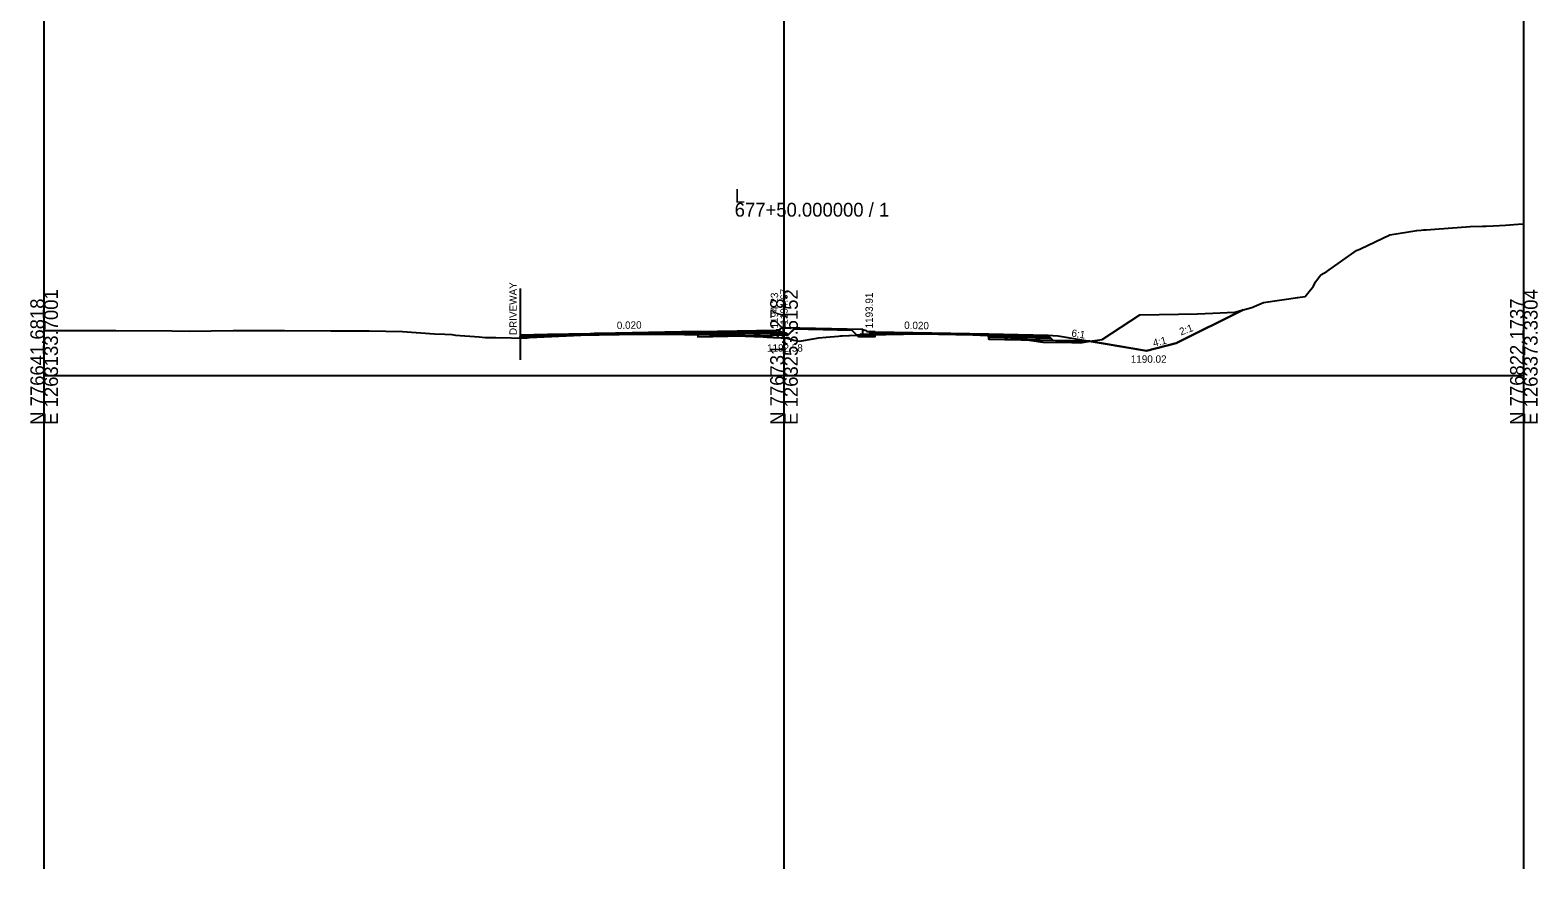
# Model space of a CAD drawing. Extents: x -41 to 1262860, y -100 to 777489.
# Drawn here: x 497.2 to 802.8, y 2050 to 2220 of the extents above; entities that cross this region are included whole.
import ezdxf

# ---------------------------------------------------------------- set-up
doc = ezdxf.new("R2010")
doc.units = 0
for name, color, linetype in [('Exist Cross Section Cell', 7, 'Continuous'), ('Exist XS Center Line Elevation Label', 7, 'Continuous'), ('Exist XS Ground Line', 7, 'Continuous'), ('Prop CMT Pvmt Course 1', 7, 'Continuous'), ('Prop CMT Pvmt Surface', 7, 'Continuous'), ('Prop CMT Shear Line', 7, 'Continuous'), ('Prop CMT Shld Paved Course 1', 7, 'Continuous'), ('Prop CMT Shld Paved Course 2', 7, 'Continuous'), ('Prop CMT Shld Paved Course 4', 7, 'Continuous'), ('Prop CMT Subgrade Earthwork', 7, 'Continuous'), ('Prop Conc Curb and Gutter', 7, 'Continuous'), ('Prop Conc Island Cover', 7, 'Continuous'), ('Prop XS Ditch Standard Text', 7, 'Continuous'), ('Prop XS Earthwork Shape', 7, 'Continuous'), ('Prop XS Elevation Labels', 7, 'Continuous'), ('Prop XS Exc Vertical Line 1', 7, 'Continuous'), ('Prop XS Exc Vertical Line 2', 7, 'Continuous'), ('Prop XS Exc Vertical Line 3', 7, 'Continuous'), ('Prop XS Finish Grade', 7, 'Continuous'), ('Prop XS Hydro Elevations', 7, 'Continuous'), ('Prop XS SE Text', 7, 'Continuous'), ('Prop XS Side Slope Text', 7, 'Continuous'), ('Scratch_Level_4', 7, 'Continuous'), ('Scratch_Level_6', 7, 'Continuous')]:
    doc.layers.add(name, color=color, linetype=linetype)

msp = doc.modelspace()

# ---------------------------------------------------------------- linework, layer by layer
at = {"layer": 'Exist Cross Section Cell'}
for p, q in [((650, 2150), (650, 2185)), ((500, 2150), (650, 2150)), ((650, 2150), (800, 2150))]:
    msp.add_line(p, q, dxfattribs=at)
at = {"layer": 'Exist XS Ground Line'}
msp.add_lwpolyline([(500, 2159.12), (503.29, 2159.11), (507.58, 2159.1), (514.52, 2159.1), (525.89, 2159.03), (529.43, 2158.99), (538.31, 2159.11), (543.77, 2159.09), (545.28, 2159.11), (546.19, 2159.11), (548.74, 2159.09), (558.13, 2159.05), (559.47, 2159.04), (562.85, 2159.03), (565.88, 2159.02), (572.63, 2158.89), (579.14, 2158.45), (581.2, 2158.39), (582.67, 2158.3), (583.4, 2158.2), (588.19, 2157.86), (589.38, 2157.71), (591.6, 2157.69), (597.83, 2157.56), (597.96, 2157.61), (598.4, 2157.7), (608.81, 2158.17), (611.05, 2158.27), (622.1, 2158.4), (623.45, 2158.41), (624.74, 2158.39), (634.91, 2158.23), (645.76, 2157.81), (646.61, 2157.78), (647.5, 2157.74), (647.56, 2157.74), (648.19, 2157.7), (650.62, 2157.54), (652.02, 2157.16), (653.11, 2156.95), (656.33, 2157.48), (657.02, 2157.61), (658.52, 2157.74), (661.02, 2157.97), (661.46, 2158.02), (661.8, 2158.03), (665.75, 2158.23), (667, 2158.25), (677.89, 2158.42), (688.3, 2158.26), (689.75, 2158.24), (690.25, 2158.2), (695, 2157.82), (697.85, 2157.43), (702.5, 2156.79), (708.34, 2156.68), (710.1, 2156.64), (711.22, 2156.83), (714.5, 2157.27), (722.14, 2162.31), (722.16, 2162.32), (722.18, 2162.32), (733.84, 2162.51), (736.95, 2162.61), (739.88, 2162.79), (741.4, 2162.84), (744.87, 2163.81), (747.25, 2164.82), (754.18, 2165.83), (755.64, 2165.99), (756.21, 2166.67), (757.37, 2168.13), (757.75, 2168.97), (758.86, 2170.4), (760.03, 2171.07), (765.6, 2175.03), (766.05, 2175.33), (766.88, 2175.7), (772.83, 2178.52), (778.29, 2179.4), (779.17, 2179.47), (779.66, 2179.51), (780.17, 2179.54), (781.96, 2179.68), (787.36, 2180.07), (788.28, 2180.13), (789.15, 2180.18), (791.65, 2180.24), (792.38, 2180.28), (793.77, 2180.33), (796.26, 2180.49), (798.83, 2180.65), (800, 2180.72)], dxfattribs=at)
at = {"layer": 'Prop CMT Pvmt Course 1'}
for p, q in [((632.5, 2158.65), (648.39, 2158.97)), ((648.39, 2158.97), (648.39, 2159.22)), ((667.5, 2158.9), (667.5, 2158.65)), ((668.5, 2158.63), (667.5, 2158.65))]:
    msp.add_line(p, q, dxfattribs=at)
for points in [[(596.5, 2158.18), (596.5, 2157.93), (596.5, 2157.93), (602.04, 2158.04), (602.04, 2158.04), (610.72, 2158.21), (610.72, 2158.21), (611.09, 2158.22), (611.09, 2158.22), (611.51, 2158.23), (611.51, 2158.23), (611.93, 2158.24), (611.93, 2158.24), (612.28, 2158.24), (612.28, 2158.24), (612.53, 2158.25), (612.53, 2158.25), (632.5, 2158.65), (632.5, 2158.9), (632.5, 2158.9), (612.53, 2158.5), (612.53, 2158.5), (612.28, 2158.49), (612.28, 2158.49), (611.93, 2158.49), (611.93, 2158.49), (611.51, 2158.48), (611.51, 2158.48), (611.09, 2158.47), (611.09, 2158.47), (610.72, 2158.46), (610.72, 2158.46), (602.04, 2158.29), (602.04, 2158.29), (596.5, 2158.18), (596.5, 2158.18), (596.5, 2158.18)], [(691.5, 2158.42), (691.5, 2158.17), (691.5, 2158.17), (668.5, 2158.63), (668.5, 2158.63), (668.5, 2158.63), (668.5, 2158.63), (668.5, 2158.88), (668.5, 2158.88), (668.5, 2158.88), (668.5, 2158.88), (668.5, 2158.88), (691.5, 2158.42), (691.5, 2158.42), (691.5, 2158.42)]]:
    msp.add_lwpolyline(points, dxfattribs=at)
at = {"layer": 'Prop CMT Pvmt Surface'}
for p, q in [((632.5, 2158.9), (648.39, 2159.22)), ((668.5, 2158.88), (667.5, 2158.9)), ((668.5, 2158.88), (691.5, 2158.42)), ((691.5, 2158.42), (703.5, 2158.18))]:
    msp.add_line(p, q, dxfattribs=at)
msp.add_lwpolyline([(596.5, 2158.18), (596.5, 2158.18), (596.5, 2158.18), (596.5, 2158.18), (596.5, 2158.18), (596.5, 2158.18), (596.5, 2158.18), (596.5, 2158.18), (632.5, 2158.9), (632.5, 2158.9)], dxfattribs=at)
at = {"layer": 'Prop CMT Shear Line'}
msp.add_line((596.5, 2167.62), (596.5, 2153.18), dxfattribs=at)
at = {"layer": 'Prop CMT Shld Paved Course 1'}
for p, q in [((691.5, 2158.42), (691.5, 2158.42)), ((691.5, 2158.42), (691.5, 2158.42)), ((691.5, 2158.42), (691.5, 2158.17)), ((691.5, 2158.17), (691.5, 2158.17)), ((691.5, 2158.17), (703.76, 2157.92)), ((695.5, 2158.34), (695.5, 2158.34)), ((703.76, 2157.92), (703.5, 2158.18))]:
    msp.add_line(p, q, dxfattribs=at)
at = {"layer": 'Prop CMT Shld Paved Course 2'}
for p, q in [((602.04, 2158.04), (608.81, 2158.18)), ((608.81, 2158.17), (602.04, 2157.86)), ((608.81, 2158.18), (610.72, 2158.21)), ((609.11, 2158.18), (608.81, 2158.17)), ((608.81, 2158.18), (608.81, 2158.18)), ((608.81, 2158.18), (608.81, 2158.18)), ((608.81, 2158.17), (608.81, 2158.17)), ((608.81, 2158.17), (608.81, 2158.17)), ((610.72, 2158.21), (609.11, 2158.18)), ((609.11, 2158.18), (609.11, 2158.18)), ((611.05, 2158.22), (610.72, 2158.21)), ((610.72, 2158.21), (611.05, 2158.22)), ((610.72, 2158.21), (610.72, 2158.21)), ((610.72, 2158.21), (610.72, 2158.21)), ((611.09, 2158.22), (611.05, 2158.22)), ((611.05, 2158.22), (611.05, 2158.22)), ((611.05, 2158.22), (611.09, 2158.22)), ((611.51, 2158.23), (611.09, 2158.22)), ((611.09, 2158.22), (611.51, 2158.23)), ((611.93, 2158.24), (611.51, 2158.23)), ((611.51, 2158.23), (611.93, 2158.24)), ((611.51, 2158.23), (611.51, 2158.23)), ((611.51, 2158.23), (611.51, 2158.23)), ((612.28, 2158.24), (611.93, 2158.24)), ((611.93, 2158.24), (611.93, 2158.24)), ((611.93, 2158.24), (611.93, 2158.24)), ((611.93, 2158.24), (612.28, 2158.24)), ((612.53, 2158.25), (612.28, 2158.24)), ((612.28, 2158.24), (612.53, 2158.25)), ((612.28, 2158.24), (612.28, 2158.24)), ((612.28, 2158.24), (612.28, 2158.24)), ((612.53, 2158.25), (622.1, 2158.44)), ((616.98, 2158.34), (612.53, 2158.25)), ((612.53, 2158.25), (612.53, 2158.25)), ((612.53, 2158.25), (612.53, 2158.25)), ((622.1, 2158.4), (616.98, 2158.34)), ((616.98, 2158.34), (616.98, 2158.34)), ((616.98, 2158.34), (616.98, 2158.34)), ((616.98, 2158.34), (616.98, 2158.34)), ((622.1, 2158.44), (623.45, 2158.47)), ((622.1, 2158.44), (622.1, 2158.44)), ((622.1, 2158.44), (622.1, 2158.44)), ((623.45, 2158.41), (622.1, 2158.4)), ((622.1, 2158.4), (622.1, 2158.4)), ((623.45, 2158.47), (624.74, 2158.49)), ((624.74, 2158.39), (623.45, 2158.41)), ((624.74, 2158.49), (632.5, 2158.65)), ((624.74, 2158.49), (624.74, 2158.49)), ((631.18, 2158.29), (624.74, 2158.39)), ((624.74, 2158.39), (624.74, 2158.39)), ((632.5, 2158.32), (631.18, 2158.29)), ((631.18, 2158.29), (631.18, 2158.29)), ((632.5, 2158.65), (632.5, 2158.65)), ((632.5, 2158.65), (632.5, 2158.65)), ((632.5, 2158.65), (632.5, 2158.32)), ((632.5, 2158.32), (648.39, 2158.63)), ((632.5, 2158.32), (632.5, 2158.32)), ((648.39, 2158.97), (648.39, 2158.63)), ((648.39, 2158.63), (648.39, 2158.63)), ((667.5, 2158.32), (667.5, 2158.65)), ((668.5, 2158.3), (667.5, 2158.32)), ((668.5, 2158.3), (668.5, 2158.63)), ((668.5, 2158.63), (668.5, 2158.63)), ((668.5, 2158.63), (668.5, 2158.63)), ((668.5, 2158.63), (668.5, 2158.63)), ((668.5, 2158.63), (677.89, 2158.44)), ((669.15, 2158.28), (668.5, 2158.3)), ((668.5, 2158.3), (668.5, 2158.3)), ((668.5, 2158.3), (668.5, 2158.3)), ((677.89, 2158.42), (669.15, 2158.28)), ((669.15, 2158.28), (669.15, 2158.28)), ((669.15, 2158.28), (669.15, 2158.28)), ((677.89, 2158.44), (677.89, 2158.44)), ((677.89, 2158.44), (677.89, 2158.44)), ((677.89, 2158.44), (677.89, 2158.44)), ((677.89, 2158.44), (677.89, 2158.44)), ((677.89, 2158.44), (688.3, 2158.23)), ((682.75, 2158.34), (677.89, 2158.42)), ((677.89, 2158.42), (677.89, 2158.42)), ((688.3, 2158.23), (682.75, 2158.34)), ((682.75, 2158.34), (682.75, 2158.34)), ((682.75, 2158.34), (682.75, 2158.34)), ((682.75, 2158.34), (682.75, 2158.34)), ((689.75, 2158.2), (688.3, 2158.23)), ((688.3, 2158.23), (688.3, 2158.23)), ((688.3, 2158.23), (688.3, 2158.23)), ((688.3, 2158.23), (688.3, 2158.23)), ((688.3, 2158.23), (688.3, 2158.23)), ((688.3, 2158.23), (689.75, 2158.2)), ((690.25, 2158.19), (689.75, 2158.2)), ((689.75, 2158.2), (689.75, 2158.2)), ((689.75, 2158.2), (689.75, 2158.2)), ((689.75, 2158.2), (690.25, 2158.19)), ((690.25, 2158.19), (690.25, 2158.19)), ((690.25, 2158.19), (691.5, 2158.17)), ((690.39, 2158.19), (690.25, 2158.19)), ((690.25, 2158.19), (690.25, 2158.19)), ((690.25, 2158.19), (690.25, 2158.19)), ((690.25, 2158.19), (690.25, 2158.19)), ((691.5, 2158.1), (690.39, 2158.19)), ((690.39, 2158.19), (690.39, 2158.19)), ((690.39, 2158.19), (690.39, 2158.19)), ((691.5, 2158.17), (691.5, 2158.17)), ((691.5, 2158.17), (691.5, 2158.17)), ((691.5, 2158.17), (691.5, 2157.84)), ((691.5, 2158.17), (691.5, 2158.17)), ((691.5, 2158.17), (691.5, 2158.1)), ((596.5, 2157.93), (597.83, 2157.96)), ((596.5, 2157.6), (596.5, 2157.93)), ((596.5, 2157.93), (596.5, 2157.93)), ((597.83, 2157.62), (596.5, 2157.6)), ((596.5, 2157.6), (596.5, 2157.6)), ((597.83, 2157.96), (597.83, 2157.96)), ((597.83, 2157.96), (597.96, 2157.96)), ((597.96, 2157.63), (597.83, 2157.62)), ((597.83, 2157.62), (597.83, 2157.62)), ((597.96, 2157.96), (598.4, 2157.97)), ((598.04, 2157.63), (597.96, 2157.63)), ((598.4, 2157.7), (598.04, 2157.63)), ((598.04, 2157.63), (598.04, 2157.63)), ((598.4, 2157.97), (602.04, 2158.04)), ((598.4, 2157.97), (598.4, 2157.97)), ((598.4, 2157.97), (598.4, 2157.97)), ((598.4, 2157.97), (598.4, 2157.97)), ((602.04, 2157.86), (598.4, 2157.7)), ((598.4, 2157.7), (598.4, 2157.7)), ((598.4, 2157.7), (598.4, 2157.7)), ((598.4, 2157.7), (598.4, 2157.7)), ((691.5, 2157.84), (691.5, 2157.84)), ((691.5, 2157.84), (704.1, 2157.58)), ((695.76, 2158.08), (695.76, 2158.08)), ((704.1, 2157.58), (703.76, 2157.92))]:
    msp.add_line(p, q, dxfattribs=at)
at = {"layer": 'Prop CMT Shld Paved Course 4'}
for p, q in [((631.18, 2158.29), (632.5, 2158.27)), ((632.5, 2158.32), (632.5, 2157.86)), ((632.5, 2157.86), (650.84, 2158.22)), ((648.39, 2158.63), (650.39, 2158.67)), ((650.39, 2158.67), (650.84, 2158.22)), ((665.5, 2158.36), (665.05, 2157.91)), ((667.5, 2158.32), (665.5, 2158.36)), ((668.5, 2157.84), (668.5, 2158.3)), ((669.15, 2158.28), (668.5, 2158.27)), ((596.5, 2157.59), (596.5, 2157.6)), ((597.83, 2157.56), (596.5, 2157.59)), ((597.96, 2157.61), (597.83, 2157.56)), ((598.04, 2157.63), (597.96, 2157.61)), ((668.5, 2157.84), (665.05, 2157.91)), ((691.5, 2157.84), (691.5, 2157.84)), ((691.5, 2157.84), (691.5, 2157.84)), ((691.5, 2157.84), (691.5, 2157.38)), ((691.5, 2157.38), (704.56, 2157.12)), ((696.1, 2157.74), (696.1, 2157.74)), ((696.6, 2157.73), (696.6, 2157.73)), ((704.56, 2157.12), (704.1, 2157.58))]:
    msp.add_line(p, q, dxfattribs=at)
at = {"layer": 'Prop CMT Subgrade Earthwork'}
for p, q in [((632.5, 2158.27), (632.5, 2157.86)), ((632.5, 2157.86), (650.84, 2158.22)), ((650.84, 2158.22), (652.24, 2159.62)), ((665.05, 2157.91), (663.56, 2159.39)), ((668.5, 2157.84), (668.5, 2158.27)), ((665.05, 2157.91), (668.5, 2157.84)), ((691.5, 2158.1), (691.5, 2157.38)), ((691.5, 2157.38), (711.78, 2156.97))]:
    msp.add_line(p, q, dxfattribs=at)
at = {"layer": 'Prop Conc Curb and Gutter'}
for p, q in [((649.08, 2159.23), (648.39, 2159.22)), ((648.39, 2159.22), (648.39, 2158.63)), ((648.39, 2158.63), (649.89, 2158.66)), ((649.14, 2159.31), (649.14, 2159.29)), ((649.89, 2159.66), (649.24, 2159.45)), ((649.89, 2158.66), (649.89, 2159.66)), ((649.89, 2158.66), (649.89, 2158.66)), ((666, 2159.35), (666.65, 2159.13)), ((666, 2158.35), (666, 2159.35)), ((667.5, 2158.32), (666, 2158.35)), ((666.75, 2158.99), (666.75, 2158.98)), ((666.81, 2158.91), (667.5, 2158.9)), ((667.5, 2158.32), (667.5, 2158.9))]:
    msp.add_line(p, q, dxfattribs=at)
for centre, radius, start, end in [((649.08, 2159.29), 0.0625, 271.1458, 360), ((649.29, 2159.31), 0.146, 108.435, 180), ((666.6, 2158.99), 0.146, 0, 71.565), ((666.81, 2158.98), 0.0625, 180, 268.8542)]:
    msp.add_arc(centre, radius, start, end, dxfattribs=at)
at = {"layer": 'Prop Conc Island Cover'}
for p, q in [((649.89, 2159.66), (650, 2159.67)), ((649.89, 2159.4), (649.89, 2159.4)), ((666, 2159.35), (650, 2159.67))]:
    msp.add_line(p, q, dxfattribs=at)
at = {"layer": 'Prop XS Earthwork Shape'}
for points in [[(722.14, 2162.31), (722.16, 2162.32), (722.18, 2162.32), (733.84, 2162.51), (736.95, 2162.61), (739.88, 2162.79), (741.4, 2162.84), (743.08, 2163.31), (729.5, 2156.52), (723.5, 2155.02), (711.99, 2156.94), (714.5, 2157.27)], [(632.5, 2158.27), (632.5, 2157.86), (640.46, 2158.02), (634.91, 2158.23)], [(652.02, 2157.16), (653.11, 2156.95), (656.33, 2157.48), (657.02, 2157.61), (658.52, 2157.74), (661.02, 2157.97), (661.46, 2158.02), (661.8, 2158.03), (664.77, 2158.18), (663.82, 2159.14), (651.99, 2159.38), (650.84, 2158.22), (640.46, 2158.02), (645.76, 2157.81), (646.61, 2157.78), (647.5, 2157.74), (647.56, 2157.74), (648.19, 2157.7), (650.62, 2157.54)], [(668.5, 2157.84), (668.5, 2158.27), (667, 2158.25), (665.75, 2158.23), (664.77, 2158.18), (665.05, 2157.91)], [(695, 2157.82), (697.85, 2157.43), (699.35, 2157.22), (691.5, 2157.38), (691.5, 2158.1)], [(711.22, 2156.83), (711.99, 2156.94), (711.78, 2156.97), (704.56, 2157.12), (699.35, 2157.22), (702.5, 2156.79), (708.34, 2156.68), (710.1, 2156.64)]]:
    msp.add_lwpolyline(points, close=True, dxfattribs=at)
at = {"layer": 'Prop XS Exc Vertical Line 1'}
msp.add_line((500, 2050), (500, 2250), dxfattribs=at)
at = {"layer": 'Prop XS Exc Vertical Line 2'}
msp.add_line((650, 2050), (650, 2250), dxfattribs=at)
at = {"layer": 'Prop XS Exc Vertical Line 3'}
msp.add_line((800, 2050), (800, 2250), dxfattribs=at)
at = {"layer": 'Prop XS Finish Grade'}
for p, q in [((729.5, 2156.52), (743.08, 2163.31)), ((703.5, 2158.18), (705.5, 2158.02)), ((703.5, 2158.18), (704.56, 2157.12)), ((705.5, 2158.02), (723.5, 2155.02)), ((723.5, 2155.02), (729.5, 2156.52))]:
    msp.add_line(p, q, dxfattribs=at)
at = {"layer": 'Scratch_Level_4'}
msp.add_line((800, 2050), (800, 2250), dxfattribs=at)
at = {"layer": 'Scratch_Level_6'}
msp.add_line((500, 2050), (500, 2250), dxfattribs=at)

# ---------------------------------------------------------------- texts
at = {"layer": 'Exist Cross Section Cell'}
for s, p in [('L', (640, 2185)), ('677+50.000000 / 1', (640, 2182.2))]:
    msp.add_text(s, height=2.8, dxfattribs=at).set_placement(p)
for s, p in [('E 1263133.7001', (502.8, 2140)), ('E 1263253.5152', (652.8, 2140)), ('E 1263373.3304', (802.8, 2140)), ('N 776641.6818', (500, 2140)), ('N 776731.9278', (650, 2140)), ('N 776822.1737', (800, 2140))]:
    msp.add_text(s, height=2.8, rotation=90, dxfattribs=at).set_placement(p)
at = {"layer": 'Exist XS Center Line Elevation Label'}
msp.add_text('1192.58', height=1.5, dxfattribs=at).set_placement((646.56, 2154.83))
at = {"layer": 'Prop XS Ditch Standard Text'}
msp.add_text('1190.02', height=1.5, dxfattribs=at).set_placement((720.31, 2152.58))
at = {"layer": 'Prop XS Elevation Labels'}
for s, p in [('1194.23', (648.81, 2159.55)), ('1193.91', (668.02, 2159.55))]:
    msp.add_text(s, height=1.5, rotation=90, dxfattribs=at).set_placement(p)
at = {"layer": 'Prop XS Hydro Elevations'}
for s, p in [('DRIVEWAY', (595.82, 2158.2)), ('1194.67', (650.75, 2160.3))]:
    msp.add_text(s, height=1.5, rotation=90, dxfattribs=at).set_placement(p)
at = {"layer": 'Prop XS SE Text'}
for rotation, p in [(1.1458, (616.12, 2159.41)), (358.8542, (674.35, 2159.45))]:
    msp.add_text('0.020', height=1.5, rotation=rotation, dxfattribs=at).set_placement(p)
at = {"layer": 'Prop XS Side Slope Text'}
for s, rotation, p in [('6:1', 350.5377, (708.19, 2157.92)), ('2:1', 20.1493, (730.48, 2158.1)), ('4:1', 14.0362, (724.98, 2155.81))]:
    msp.add_text(s, height=1.5, rotation=rotation, dxfattribs=at).set_placement(p)

doc.saveas('drawing.dxf')
